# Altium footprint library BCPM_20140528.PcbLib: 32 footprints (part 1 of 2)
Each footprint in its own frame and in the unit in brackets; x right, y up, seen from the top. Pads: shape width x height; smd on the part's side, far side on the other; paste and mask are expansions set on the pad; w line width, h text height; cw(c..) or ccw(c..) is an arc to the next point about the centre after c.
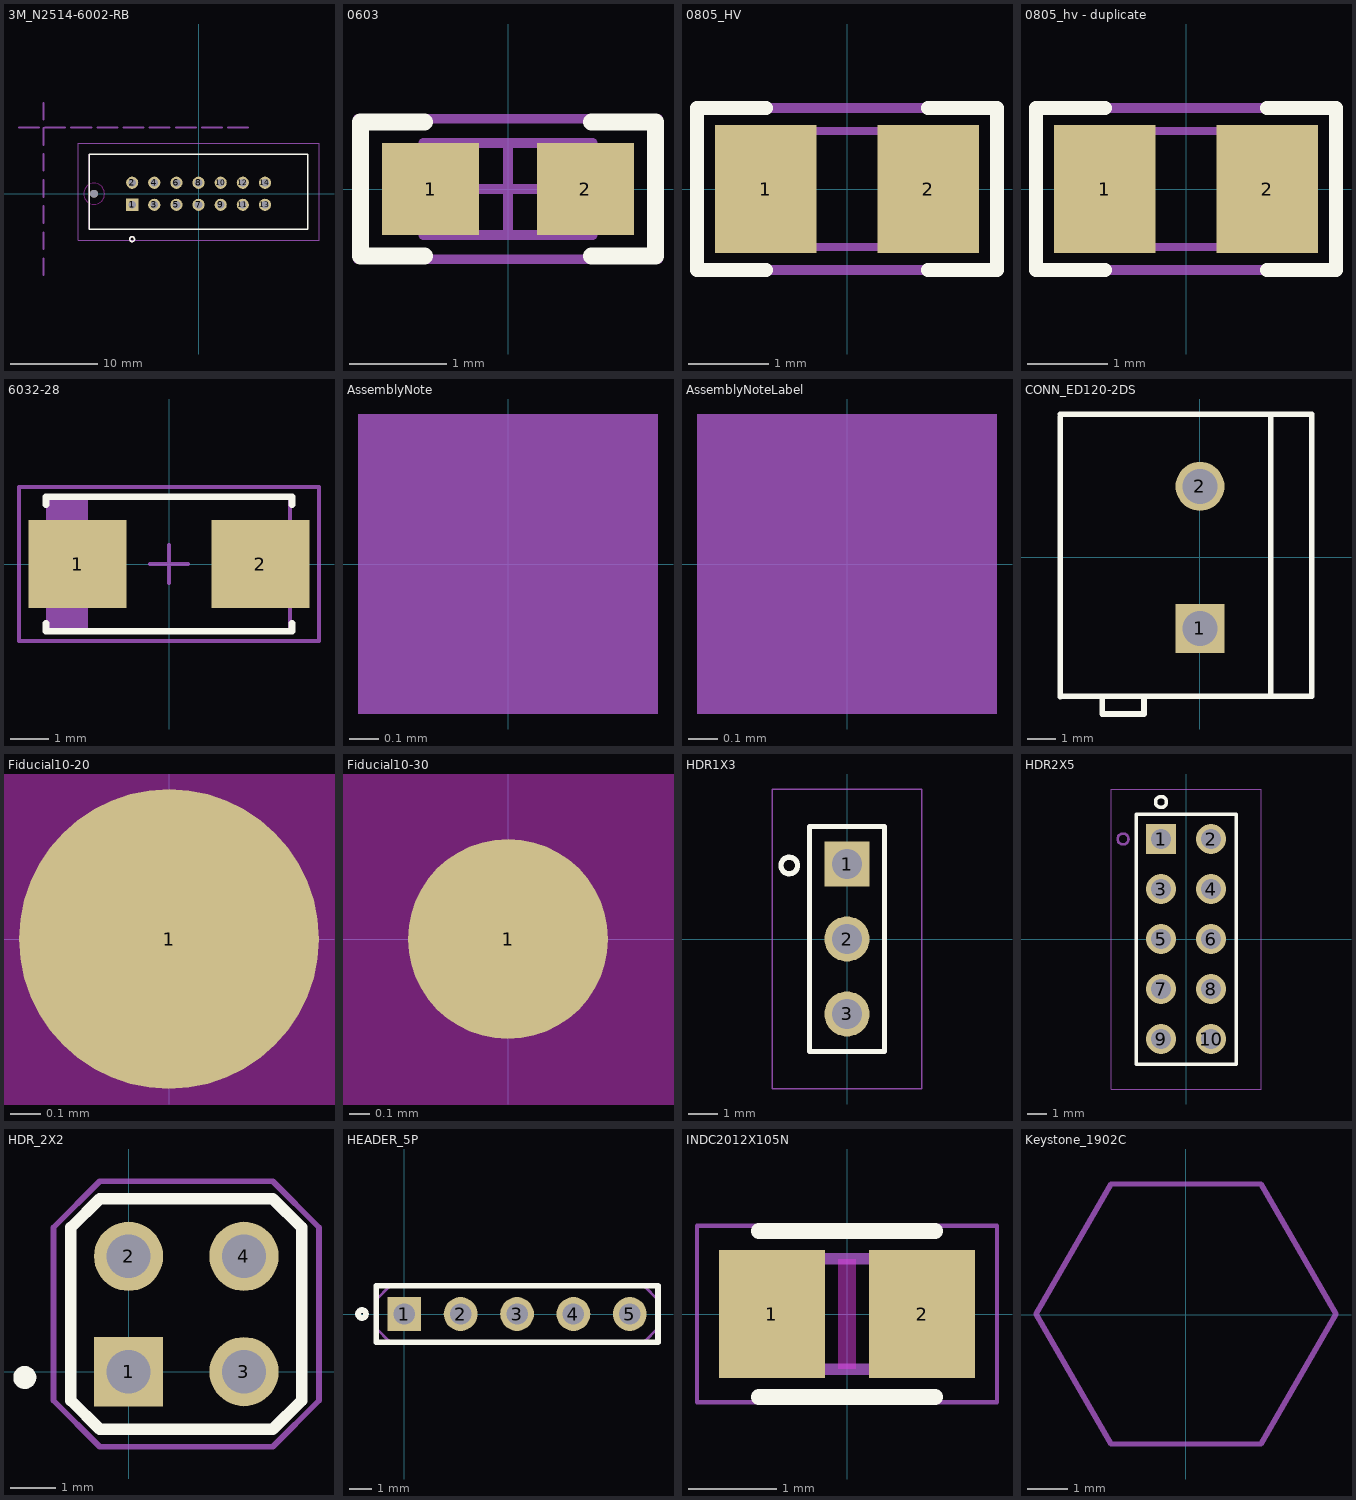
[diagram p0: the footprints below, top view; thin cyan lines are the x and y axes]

## 3M_N2514-6002-RB [mm] "CONN, HEADER, 14 POS, STRGHT GOLD"
height 9.91
pads (15):
  rect 1.4x1.4 / inner round 1.4 / far side rect 1.4x1.4 hole 0.889: 1(-7.62,-1.27)
  round 1.4 hole 0.889: 2(-7.62,1.27) 3(-5.08,-1.27) 4(-5.08,1.27) 5(-2.54,-1.27) 6(-2.54,1.27) 7(0,-1.27) 8(0,1.27) 9(2.54,-1.27) 10(2.54,1.27) 11(5.08,-1.27) 12(5.08,1.27) 13(7.62,-1.27) 14(7.62,1.27)
  round 0.889 hole 0.889 unplated mask+0.127: ""(-11.99,0)
Top Overlay:
  circle w0.178: c-7.62,-5.207 r0.279
  lines w0.178: -12.55,-4.07 -12.55,4.52 12.55,4.52 12.55,-4.07 -12.55,-4.07
  text ".Designator" at 14.351,-0.762 h1.02
Bottom Overlay:
  lines w0.178: -12.573,-4.07 -11.427,-4.07 ; -12.55,-4.07 -12.55,-3.023 ; -12.55,-2.413 -12.55,-1.499 ; -12.55,1.524 -12.55,2.438 ; -12.55,3 -12.55,4.52 -10.287,4.52 ; -10.713,-4.07 -8.427,-4.07 ; -9.573,4.52 -7.287,4.52 ; -9.446,4.52 -7.16,4.52 ; -7.713,-4.07 -5.427,-4.07 ; -6.446,4.52 -4.16,4.52 ; -4.713,-4.07 -2.427,-4.07 ; -3.446,4.52 -1.16,4.52 ; -1.713,-4.07 0.573,-4.07 ; -0.446,4.52 1.84,4.52 ; 1.287,-4.07 3.573,-4.07 ; 2.554,4.52 4.84,4.52 ; 4.287,-4.07 6.573,-4.07 ; 5.554,4.52 7.84,4.52 ; 7.287,-4.07 9.573,-4.07 ; 8.554,4.52 10.84,4.52 ; 10.287,-4.07 12.55,-4.07 12.55,-3.071 ; 11.43,4.52 12.55,4.52 12.55,3 ; 12.55,-1.953 12.55,-0.658 ; 12.55,0.46 12.55,1.755
Mechanical 5:
  circle w0.127: c-7.62,-5.207 r0.279
  lines w0.127: -12.55,-4.07 12.55,-4.07 12.55,4.52 -12.55,4.52 -12.55,-4.07
  text ".Designator" at -0.889,-0.762 h0.76
Mechanical 15:
  lines w0.05: -13.82,-5.34 13.82,-5.34 13.82,5.79 -13.82,5.79 -13.82,-5.34
Mechanical 16:
  lines w0.254: -20.605,7.62 -18.319,7.62 ; -17.78,-9.333 -17.78,-7.428 ; -17.78,-6.333 -17.78,-4.428 ; -17.78,-3.333 -17.78,-1.428 ; -17.78,-0.333 -17.78,1.572 ; -17.78,2.667 -17.78,4.572 ; -17.78,5.603 -17.78,7.508 ; -17.78,8.524 -17.78,10.429 ; -17.605,7.62 -15.319,7.62 ; -14.605,7.62 -12.319,7.62 ; -11.605,7.62 -9.319,7.62 ; -8.605,7.62 -6.319,7.62 ; -5.605,7.62 -3.319,7.62 ; -2.605,7.62 -0.319,7.62 ; 0.395,7.62 2.681,7.62 ; 3.395,7.62 5.681,7.62
Multi-Layer keep-out:
  circle w0.025: c-11.99,0 r1.206
Mechanical 17:
  text "MIN END STACKABLE DISTANCE" at -18.288,-11.049 h1
  text "MIN SIDE STACKABLE DISTANCE" at -47.498,7.239 h1
  text "RECOMMENDED BOARD THICKNESS: 62 MIL" at -16.637,2.413 h1
  text "LEAD LENGTH: 2.84 MM" at -7.874,-3.429 h1
  text "DRILL TOLERANCE FOR NPTH HOLE IS +/-3 MIL" at -20.9,0.65 h1
3D body: height 9.91, standoff 0, extent -12.55,-4.07 12.55,4.52

## 0603 [mm] "0603 from SM-752 data"
height 0.85
pads (2):
  rect 1x0.95 smd: 1(-0.8,0) 2(0.8,0)
Top Overlay:
  lines w0.178: -0.864,-0.691 -1.524,-0.691 -1.524,0.693 -0.864,0.693 ; 0.864,-0.691 1.524,-0.691 1.524,0.693 0.864,0.693
Mechanical 5:
  lines w0.1: -1.55,-0.725 1.55,-0.725 1.55,0.725 -1.55,0.725 -1.55,-0.725
  text ".Designator" at 1.346,0.381 h0.76
Mechanical 13:
  lines w0.1: -0.55,-0.475 -0.55,0.475 ; 0.55,-0.475 0.55,0.475 ; -0.875,-0.475 -0.875,0.475 0.875,0.475 0.875,-0.475 -0.875,-0.475
Mechanical 15:
  lines w0.1: -0.475,0 0.475,0 ; 0,-0.475 0,0.475 ; -1.55,-0.725 -1.55,0.725 1.55,0.725 1.55,-0.725 -1.55,-0.725
3D body: height 0.85, standoff 0, extent 0.551,-0.474 0.874,0.474
3D body: height 0.85, standoff 0, extent -0.549,-0.474 0.549,0.474
3D body: height 0.85, standoff 0, extent -0.874,-0.474 -0.551,0.474

## 0805_HV [mil] "0805 with 30mil clearance between pads"
height 43.31
pads (2):
  rect 50x63 smd: 1(-40,0) 2(40,0)
Top Overlay:
  lines w7: -40,-40 -74,-40 -74,0 -74,40 -40,40 ; 40,-40 74,-40 74,0 74,40 40,40
Mechanical 5:
  lines w5: -74,-40 -74,40 74,40 74,-40 -74,-40
  text ".Designator" at 20,15 h30
Mechanical 13:
  lines w3.94: -25.59,-28.54 -25.59,28.54 ; 25.59,-28.54 25.59,28.54 ; -43.31,-28.54 43.31,-28.54 43.31,28.54 -43.31,28.54 -43.31,-28.54
3D body: height 43.31, standoff 0, extent -43.29,-28.52 -25.61,28.52
3D body: height 43.31, standoff 0, extent -25.57,-28.52 25.57,28.52
3D body: height 43.31, standoff 0, extent 25.61,-28.52 43.29,28.52

## 0805_hv - duplicate [mil]
pads (2):
  rect 50x63 smd: 1(-40,0) 2(40,0)
Top Overlay:
  lines w7: -40,-40 -74,-40 -74,0 -74,40 -40,40 ; 40,-40 74,-40 74,0 74,40 40,40
Mechanical 5:
  lines w5: -74,-40 -74,40 74,40 74,-40 -74,-40
  text ".Designator" at -40,-15 h30
Mechanical 13:
  lines w3.94: -25.59,-28.54 -25.59,28.54 ; 25.59,-28.54 25.59,28.54 ; -43.31,-28.54 43.31,-28.54 43.31,28.54 -43.31,28.54 -43.31,-28.54
3D body: height 43.31, standoff 0, extent -43.29,-28.52 -25.61,28.52
3D body: height 43.31, standoff 0, extent -25.57,-28.52 25.57,28.52
3D body: height 43.31, standoff 0, extent 25.61,-28.52 43.29,28.52

## 6032-28 [mm] "Medium Density IPC based on Vishay Sprague 293D datasheet."
height 2.8
pads (2):
  rect 2.55x2.3 smd: 1(-2.375,0) 2(2.375,0)
Top Overlay:
  lines w0.178: -3.2,-1.539 -3.2,-1.75 3.2,-1.75 3.2,-1.539 ; -3.2,1.539 -3.2,1.75 3.2,1.75 3.2,1.539
Mechanical 5:
  rectangle: -3.15,-1.75 -2.15,1.75
  lines w0.1: -2.15,-1.75 -2.15,1.75 ; -3.15,-1.75 3.15,-1.75 3.15,1.75 -3.15,1.75 -3.15,-1.75
  text ".Designator" at 0.381,-0.635 h0.76
Mechanical 15:
  lines w0.1: -0.5,0 0.5,0 ; 0,-0.5 0,0.5 ; -3.9,-2 -3.9,2 3.9,2 3.9,-2 -3.9,-2
3D body: height 2.8, standoff 2.8, extent -3.149,-1.749 -2.151,1.749
3D body: height 2.8, standoff 0, extent -3.15,-1.75 3.15,1.75

## AssemblyNote [mm] "Assembly Note"
Mechanical 5:
  rectangle: -0.508,-0.508 0.508,0.508
  text ".Designator" at -4.191,-0.508 h0.76
  text ".Comment" at 1.143,-0.508 h0.76

## AssemblyNoteLabel [mm] "Assembly Note for PCB Labels"
Mechanical 5:
  rectangle: -0.508,-0.508 0.508,0.508
  text ".Designator" at -4.191,-0.508 h0.76
  text "Install label in silkscreened box after final wash.  Text shall be 8 pt font.  Text shall be per the Label Table in the PDF schematic." at 1.143,-0.508 h0.76

## CONN_ED120-2DS [mm] "ONSHORE"
height 13
pads (2):
  rect 1.75x1.75 hole 1.25: 1(0,-2.54)
  round 1.75 hole 1.25: 2(0,2.54)
Top Overlay:
  lines w0.2: -5,-4.985 -5,5.015 ; -5,-4.96 4,-4.96 ; -5,5.115 4,5.115 4,-4.885 ; -3.5,-4.96 -3.5,-5.6 -2,-5.6 -2,-4.96 ; 2.525,-4.95 2.525,5.05
Mechanical 5:
  lines w0.1: -5,-4.96 4,-4.96 ; -5,-4.885 -5,5.115 4,5.115 4,-4.885 ; -3.5,-4.96 -3.5,-5.6 -2,-5.6 -2,-4.96 ; 2.525,-4.875 2.525,5.125
  text ".Designator" at -1.6,-0.272 h0.76
3D body: height 13, standoff 0, extent -3.5,-5.6 -2,-4.925
3D body: height 5.7, standoff 4.3, extent -0.875,-3.204 4.125,-1.81
3D body: height 5.7, standoff 4.3, extent -0.85,1.846 4.15,3.24
3D body: height 13.1, standoff -2.5, extent -0.496,2.041 0.5,3.039
3D body: height 13.1, standoff -2.5, extent -0.496,-3.039 0.5,-2.041
3D body: height 13, standoff 0, extent -5,-4.985 4,5.115

## Fiducial10-20 [mm]
pads (1):
  round 1 smd paste-0.5 mask+0.5: 1(0,0)
Top Layer keep-out:
  circle w1.178: c0,0 r0.5

## Fiducial10-30 [mm]
pads (1):
  round 1 smd paste-0.5 mask+1: 1(0,0)
Top Layer keep-out:
  circle w1.678: c0,0 r0.75

## HDR1X3 [mil] "HDR1X3"
pads (3):
  rect 60x60 / inner round 60 / far side rect 60x60 hole 40: 1(0,100)
  round 60 hole 40: 2(0,0) 3(0,-100)
Top Overlay:
  circle w7: c-77,98 r11
  lines w7: -50,-150 50,-150 50,150 -50,150 -50,-150
  text ".Designator" at -75,-55 h40
Bottom Overlay:
  lines w7: -50.48,-112.48 -50.48,-73.11 ; -50,-18.11 -50,21.26 ; -50,60.63 -50,100 ; -50,150 25,150 ; -47.89,-149.86 2.11,-149.86 ; 39.37,-150.58 50,-150.58 50,-118.69 ; 50,-66.06 50,-26.68 ; 50,21.26 50,60.63 ; 50,100 50,150
Mechanical 5:
  circle w5: c-77,98 r11
  lines w5: -50,-150 -50,150 50,150 50,-150 -50,-150
  text ".Designator" at -70,-35 h30
Mechanical 15:
  lines w1.97: -100,-200 -100,200 100,200 100,-200 -100,-200
3D body: height 1, standoff 0, extent -50,-150 50,150

## HDR2X5 [mm] "CONN, MALE, 2.54 MM PITCH, 10-PIN"
height 8.38
pads (10):
  rect 1.52x1.52 / inner round 1.52 / far side rect 1.52x1.52 hole 1.02: 1(-1.27,5.08)
  round 1.52 hole 1.02: 2(1.27,5.08) 3(-1.27,2.54) 4(1.27,2.54) 5(-1.27,0) 6(1.27,0) 7(-1.27,-2.54) 8(1.27,-2.54) 9(-1.27,-5.08) 10(1.27,-5.08)
Top Overlay:
  circle w0.178: c-1.27,6.96 r0.279
  lines w0.178: -2.54,-6.35 -2.54,6.35 2.54,6.35 2.54,-6.35 -2.54,-6.35
  text ".Designator" at 4.191,-1.27 h1.02
Bottom Overlay:
  lines w0.178: -2.54,-6.319 -2.54,-3.429 ; -2.54,-1.43 -2.54,1.46 ; -2.54,3.57 -2.54,6.35 -0.6,6.35 ; -2.483,-6.35 -0.768,-6.35 ; 0.58,6.35 2.52,6.35 ; 0.825,-6.35 2.54,-6.35 2.54,-3.545 ; 2.54,-1.69 2.54,1.375 ; 2.54,3.31 2.54,6.35
Mechanical 5:
  circle w0.127: c-3.2,5.08 r0.279
  lines w0.127: -2.54,-6.35 2.54,-6.35 2.54,6.35 -2.54,6.35 -2.54,-6.35
  text ".Designator" at 0.254,0.254 h0.76
Mechanical 15:
  lines w0.05: -3.81,-7.62 3.81,-7.62 3.81,7.62 -3.81,7.62 -3.81,-7.62
3D body: height 8.38, standoff 0, extent -2.54,-6.35 2.54,6.35

## HDR_2X2 [mil]
pads (4):
  rect 60x60 hole 38: 1(0,0)
  round 60 hole 38: 2(0,100) 3(100,0) 4(100,100)
Top Overlay:
  circle w10: c-90,-5 r5
  lines w10: -50,-25 -50,125 -25,150 125,150 150,125 150,-25 125,-50 -25,-50 -50,-25
Mechanical 5:
  lines w5: -65,-25 -65,125 -25,165 125,165 165,125 165,-25 125,-65 -25,-65 -65,-25
  text "*" at -100,-20 h30
  text ".Designator" at 75,65 h30

## HEADER_5P [mil]
pads (5):
  rect 60x60 hole 38: 1(0,0)
  round 60 hole 38: 2(100,0) 3(200,0) 4(300,0) 5(400,0)
Top Overlay:
  circle w10: c-75,0 r7.07
  lines w10: -50,-50 -50,-25 -50,25 -50,50 450,50 450,25 450,-25 450,-50 -50,-50
Mechanical 5:
  lines w5: 420,-50 -25,-50 -50,-25 -50,25 -25,50 420,50 ; 425,-50 450,-25 450,25 425,50
  text ".Designator" at 265.47,-40 h30
  text "*" at -39,-18 h30

## INDC2012X105N [mm] "INDUCTOR, 0805"
height 1.05
pads (2):
  rect 1.2x1.45 smd: 1(-0.85,0) 2(0.85,0)
Top Layer keep-out:
  rectangle: -0.102,-0.625 0.102,0.625
Top Overlay:
  lines w0.178: -1,-0.941 1,-0.941 ; -1,0.941 1,0.941
  text ".Designator" at 1.397,-1.397 h1.02
Mechanical 5:
  lines w0.127: -1,-0.625 -1,0.625 1,0.625 1,-0.625 -1,-0.625
  text ".Designator" at 0.889,-1.143 h0.76
Mechanical 15:
  lines w0.05: -1.7,-1 -1.7,1 1.7,1 1.7,-1 -1.7,-1
3D body: height 1.05, standoff 0, extent -1,-0.625 1,0.625

## Keystone_1902C [mil] "Hex Standoff, 4-40 threaded, nylon"
height 500
pads (1):
  round 1 on Mech3: 0(0,0)
Mechanical 5:
  lines w5: -145.29,0.49 -72.56,126.47 72.92,126.47 145.65,0.49 72.92,-125.49 -72.56,-125.49 -145.29,0.49
  text ".Designator" at -60,-20 h30
3D body: height 501, standoff 1, extent -144.95,-125.98 146,125.98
